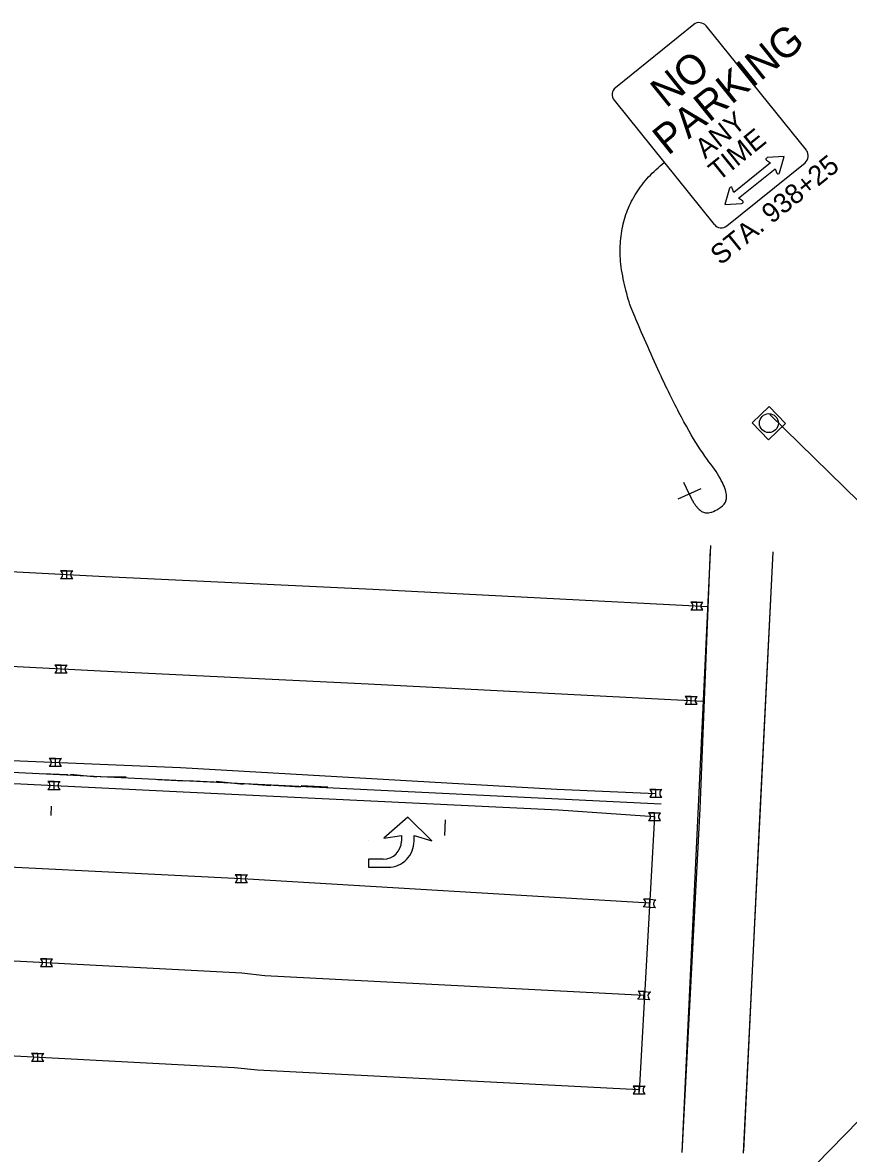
# Model space of a CAD drawing. Extents: x 1847379 to 1850904, y 217032 to 220169.
# Drawn here: x 1847885.3 to 1847990, y 218864.8 to 219008.1 of the extents above; entities that cross this region are included whole.
import ezdxf

# ---------------------------------------------------------------- set-up
doc = ezdxf.new("R2010")
doc.units = 0
for name, color, linetype in [('GE_X_Alignment_100_Stations', 7, 'Continuous'), ('PM_P_Cells', 7, 'Continuous'), ('PM_P_Channelizing_Line', 7, 'Continuous'), ('PM_P_CL_Double_Solid', 7, 'Continuous'), ('PM_P_Crosswalk', 7, 'Continuous'), ('PM_P_Edge_Line', 7, 'Continuous'), ('PM_P_Lane_Line', 7, 'Continuous'), ('PM_P_Stop_Line', 7, 'Continuous'), ('PM_X_Cells', 7, 'Continuous'), ('PM_X_Crosswalk', 7, 'Continuous'), ('RD_X_Bumper_Block', 7, 'Continuous'), ('SG_X_Wiring', 7, 'Continuous'), ('SN_X_Foundation', 7, 'Continuous'), ('SN_X_Public', 7, 'Continuous')]:
    doc.layers.add(name, color=color, linetype=linetype)

msp = doc.modelspace()

# ---------------------------------------------------------------- linework, layer by layer
at = {"layer": 'GE_X_Alignment_100_Stations'}
for p, q in [((1847888.88, 218907.64), (1847888.95, 218908.84)), ((1847938.82, 218905.09), (1847938.92, 218907.09))]:
    msp.add_line(p, q, dxfattribs=at)
at = {"layer": 'PM_P_Cells'}
for p, q in [((1847890.87, 218938.66), (1847890.1, 218938.66)), ((1847890.1, 218938.66), (1847890.87, 218938.66)), ((1847890.87, 218938.66), (1847891.64, 218938.66)), ((1847890.87, 218937.68), (1847890.87, 218938.66)), ((1847890.1, 218937.68), (1847890.87, 218937.68)), ((1847890.1, 218937.68), (1847890.87, 218937.68)), ((1847890.87, 218937.68), (1847891.64, 218937.68)), ((1847970.77, 218934.69), (1847970, 218934.69)), ((1847970, 218934.69), (1847970.77, 218934.69)), ((1847970, 218933.71), (1847970.77, 218933.71)), ((1847970, 218933.71), (1847970.77, 218933.71)), ((1847970.77, 218934.69), (1847971.54, 218934.69)), ((1847970.77, 218933.71), (1847970.77, 218934.69)), ((1847970.77, 218933.71), (1847971.54, 218933.71)), ((1847890.15, 218926.71), (1847889.38, 218926.71)), ((1847889.38, 218926.71), (1847890.15, 218926.71)), ((1847890.15, 218926.71), (1847890.92, 218926.71)), ((1847890.15, 218925.73), (1847890.15, 218926.71)), ((1847889.38, 218925.73), (1847890.15, 218925.73)), ((1847889.38, 218925.73), (1847890.15, 218925.73)), ((1847890.15, 218925.73), (1847890.92, 218925.73)), ((1847970.05, 218922.73), (1847969.28, 218922.73)), ((1847969.28, 218922.73), (1847970.05, 218922.73)), ((1847970.05, 218922.73), (1847970.83, 218922.73)), ((1847970.05, 218921.76), (1847970.05, 218922.73)), ((1847969.28, 218921.76), (1847970.05, 218921.76)), ((1847969.28, 218921.76), (1847970.05, 218921.76)), ((1847970.05, 218921.76), (1847970.83, 218921.76)), ((1847889.44, 218914.87), (1847888.67, 218914.87)), ((1847888.67, 218914.87), (1847889.44, 218914.87)), ((1847888.67, 218913.89), (1847889.44, 218913.89)), ((1847888.67, 218913.89), (1847889.44, 218913.89)), ((1847889.44, 218914.87), (1847890.21, 218914.87)), ((1847889.44, 218913.89), (1847889.44, 218914.87)), ((1847889.44, 218913.89), (1847890.21, 218913.89)), ((1847889.26, 218911.93), (1847888.49, 218911.93)), ((1847888.49, 218911.93), (1847889.26, 218911.93)), ((1847888.49, 218910.95), (1847889.26, 218910.95)), ((1847888.49, 218910.95), (1847889.26, 218910.95)), ((1847889.26, 218911.93), (1847890.03, 218911.93)), ((1847889.26, 218910.95), (1847889.26, 218911.93)), ((1847889.26, 218910.95), (1847890.03, 218910.95)), ((1847965.57, 218910.94), (1847964.8, 218910.94)), ((1847964.8, 218910.94), (1847965.57, 218910.94)), ((1847965.57, 218910.94), (1847966.34, 218910.94)), ((1847965.57, 218909.96), (1847965.57, 218910.94)), ((1847964.8, 218909.96), (1847965.57, 218909.96)), ((1847964.8, 218909.96), (1847965.57, 218909.96)), ((1847965.57, 218909.96), (1847966.34, 218909.96)), ((1847965.4, 218907.99), (1847964.63, 218907.99)), ((1847964.63, 218907.99), (1847965.4, 218907.99)), ((1847965.4, 218907.99), (1847966.17, 218907.99)), ((1847965.4, 218907.02), (1847965.4, 218907.99)), ((1847934.11, 218907.43), (1847931.07, 218904.76)), ((1847937.15, 218904.43), (1847934.11, 218907.43)), ((1847964.63, 218907.02), (1847965.4, 218907.02)), ((1847964.63, 218907.02), (1847965.4, 218907.02)), ((1847965.4, 218907.02), (1847966.17, 218907.02)), ((1847931.07, 218904.76), (1847933.31, 218905.09)), ((1847933.31, 218905.09), (1847933.31, 218904.39)), ((1847934.91, 218904.43), (1847934.91, 218905.09)), ((1847934.91, 218905.09), (1847937.15, 218904.43)), ((1847929.15, 218904.43), (1847929.15, 218904.43)), ((1847937.15, 218904.43), (1847937.15, 218904.43)), ((1847931.01, 218902.09), (1847929.15, 218902.09)), ((1847929.15, 218902.09), (1847929.15, 218901.09)), ((1847929.15, 218901.09), (1847931.63, 218901.09)), ((1847913, 218900.11), (1847912.23, 218900.11)), ((1847912.23, 218900.11), (1847913, 218900.11)), ((1847913, 218900.11), (1847913.77, 218900.11)), ((1847913, 218899.13), (1847913, 218900.11)), ((1847912.23, 218899.13), (1847913, 218899.13)), ((1847912.23, 218899.13), (1847913, 218899.13)), ((1847913, 218899.13), (1847913.77, 218899.13)), ((1847964.82, 218897.02), (1847964.05, 218897.07)), ((1847964.05, 218897.07), (1847964.82, 218897.02)), ((1847964.75, 218896.04), (1847964.82, 218897.02)), ((1847964.82, 218897.02), (1847965.59, 218896.96)), ((1847963.98, 218896.09), (1847964.75, 218896.04)), ((1847963.98, 218896.09), (1847964.75, 218896.04)), ((1847964.75, 218896.04), (1847965.52, 218895.99)), ((1847888.31, 218889.47), (1847887.54, 218889.47)), ((1847887.54, 218889.47), (1847888.31, 218889.47)), ((1847888.31, 218889.47), (1847889.08, 218889.47)), ((1847888.31, 218888.49), (1847888.31, 218889.47)), ((1847887.54, 218888.49), (1847888.31, 218888.49)), ((1847887.54, 218888.49), (1847888.31, 218888.49)), ((1847888.31, 218888.49), (1847889.08, 218888.49)), ((1847964.11, 218885.33), (1847963.34, 218885.39)), ((1847963.34, 218885.39), (1847964.11, 218885.33)), ((1847964.04, 218884.36), (1847964.11, 218885.33)), ((1847964.11, 218885.33), (1847964.88, 218885.27)), ((1847963.27, 218884.41), (1847964.04, 218884.36)), ((1847963.27, 218884.41), (1847964.04, 218884.36)), ((1847964.04, 218884.36), (1847964.81, 218884.3)), ((1847887.19, 218877.48), (1847886.42, 218877.48)), ((1847886.42, 218877.48), (1847887.19, 218877.48)), ((1847886.42, 218876.51), (1847887.19, 218876.51)), ((1847886.42, 218876.51), (1847887.19, 218876.51)), ((1847887.19, 218877.48), (1847887.96, 218877.48)), ((1847887.19, 218876.51), (1847887.19, 218877.48)), ((1847887.19, 218876.51), (1847887.96, 218876.51)), ((1847963.46, 218873.35), (1847962.69, 218873.35)), ((1847962.69, 218873.35), (1847963.46, 218873.35)), ((1847962.69, 218872.37), (1847963.46, 218872.37)), ((1847962.69, 218872.37), (1847963.46, 218872.37)), ((1847963.46, 218873.35), (1847964.23, 218873.35)), ((1847963.46, 218872.37), (1847963.46, 218873.35)), ((1847963.46, 218872.37), (1847964.23, 218872.37))]:
    msp.add_line(p, q, dxfattribs=at)
msp.add_lwpolyline([(1847966.24, 218909.06), (1847864.82, 218914.02), (1847726.41, 218921.61), (1847615.2, 218928.22)], dxfattribs=at)
for centre, radius, start, end in [((1847889.79, 218938.17), 0.576, 301.9738, 58.0262), ((1847889.79, 218938.17), 0.576, 301.9738, 58.0262), ((1847891.94, 218938.17), 0.576, 121.9738, 238.0262), ((1847969.7, 218934.2), 0.576, 301.9738, 58.0262), ((1847969.7, 218934.2), 0.576, 301.9738, 58.0262), ((1847971.85, 218934.2), 0.576, 121.9738, 238.0262), ((1847889.07, 218926.22), 0.576, 301.9738, 58.0262), ((1847889.07, 218926.22), 0.576, 301.9738, 58.0262), ((1847891.22, 218926.22), 0.576, 121.9738, 238.0262), ((1847968.98, 218922.25), 0.576, 301.9738, 58.0262), ((1847968.98, 218922.25), 0.576, 301.9738, 58.0262), ((1847971.13, 218922.25), 0.576, 121.9738, 238.0262), ((1847888.36, 218914.38), 0.576, 301.9738, 58.0262), ((1847888.36, 218914.38), 0.576, 301.9738, 58.0262), ((1847890.51, 218914.38), 0.576, 121.9738, 238.0262), ((1847888.19, 218911.44), 0.576, 301.9738, 58.0262), ((1847888.19, 218911.44), 0.576, 301.9738, 58.0262), ((1847890.34, 218911.44), 0.576, 121.9738, 238.0262), ((1847964.49, 218910.45), 0.576, 301.9738, 58.0262), ((1847964.49, 218910.45), 0.576, 301.9738, 58.0262), ((1847966.64, 218910.45), 0.576, 121.9738, 238.0262), ((1847964.33, 218907.5), 0.576, 301.9738, 58.0262), ((1847964.33, 218907.5), 0.576, 301.9738, 58.0262), ((1847966.48, 218907.5), 0.576, 121.9738, 238.0262), ((1847931.01, 218904.39), 2.3, 270, 360), ((1847931.63, 218904.37), 3.28, 270, 0.9085), ((1847911.93, 218899.62), 0.576, 301.9738, 58.0262), ((1847911.93, 218899.62), 0.576, 301.9738, 58.0262), ((1847914.08, 218899.62), 0.576, 121.9738, 238.0262), ((1847963.71, 218896.6), 0.576, 297.9977, 54.05), ((1847963.71, 218896.6), 0.576, 297.9977, 54.05), ((1847965.86, 218896.45), 0.576, 117.9977, 234.05), ((1847887.23, 218888.98), 0.576, 301.9738, 58.0262), ((1847887.23, 218888.98), 0.576, 301.9738, 58.0262), ((1847889.39, 218888.98), 0.576, 121.9738, 238.0262), ((1847963, 218884.92), 0.576, 297.8201, 53.8724), ((1847963, 218884.92), 0.576, 297.8201, 53.8724), ((1847965.15, 218884.77), 0.576, 117.8201, 233.8724), ((1847886.12, 218876.99), 0.576, 301.9738, 58.0262), ((1847886.12, 218876.99), 0.576, 301.9738, 58.0262), ((1847888.27, 218876.99), 0.576, 121.9738, 238.0262), ((1847962.38, 218872.86), 0.576, 301.9738, 58.0262), ((1847962.38, 218872.86), 0.576, 301.9738, 58.0262), ((1847964.53, 218872.86), 0.576, 121.9738, 238.0262)]:
    msp.add_arc(centre, radius, start, end, dxfattribs=at)
at = {"layer": 'PM_P_Channelizing_Line'}
msp.add_lwpolyline([(1847964.79, 218896.53), (1847913.83, 218899.57), (1847868.37, 218901.85), (1847801.67, 218905.51), (1847760.88, 218907.57), (1847747.13, 218908.37), (1847700.27, 218911.19), (1847652.77, 218914.09), (1847633.42, 218915.04)], dxfattribs=at)
at = {"layer": 'PM_P_CL_Double_Solid'}
for points in [[(1847490, 218937.41), (1847521.99, 218935.72), (1847549.87, 218933.62), (1847611.92, 218929.38), (1847659.1, 218926.63), (1847712.21, 218923.52), (1847759.64, 218920.72), (1847810.63, 218918.2), (1847858.38, 218915.68), (1847905.32, 218913.72), (1847953.04, 218910.96), (1847965.57, 218910.45)], [(1847489.25, 218926.47), (1847521.5, 218924.19), (1847547.23, 218922.25), (1847572.89, 218923.43), (1847613.93, 218927.4), (1847658.9, 218924.58), (1847711.95, 218921.4), (1847759.89, 218918.36), (1847810.62, 218915.58), (1847858.37, 218912.98), (1847905.65, 218910.62), (1847953.25, 218908.34), (1847965.4, 218907.5)]]:
    msp.add_lwpolyline(points, dxfattribs=at)
at = {"layer": 'PM_P_Crosswalk'}
for p, q in [((1847972.51, 218941.88), (1847968.88, 218864.98)), ((1847980.4, 218941.05), (1847976.66, 218864.85))]:
    msp.add_line(p, q, dxfattribs=at)
at = {"layer": 'PM_P_Edge_Line'}
for points in [[(1847552.47, 218957.76), (1847602.87, 218954.43), (1847648.99, 218950.94), (1847698.22, 218948.16), (1847749.1, 218945.08), (1847799.04, 218942.57), (1847847.68, 218940.46), (1847895.74, 218937.94), (1847929.69, 218936.33), (1847972.19, 218934.13)], [(1847963.46, 218872.86), (1847915.07, 218875.36), (1847912.14, 218875.67), (1847866.67, 218878.08), (1847793.75, 218882.07), (1847746.55, 218884.86), (1847706.33, 218887.44), (1847651.18, 218890.91), (1847631.45, 218892.5), (1847577.19, 218896.26), (1847520.38, 218900.5), (1847487.61, 218902.76)]]:
    msp.add_lwpolyline(points, dxfattribs=at)
at = {"layer": 'PM_P_Lane_Line'}
for points in [[(1847490.83, 218949.44), (1847551.31, 218945.81), (1847602.03, 218942.46), (1847648.2, 218938.97), (1847697.52, 218936.18), (1847748.44, 218933.1), (1847798.48, 218930.58), (1847847.11, 218928.48), (1847895.15, 218925.96), (1847929.1, 218924.34), (1847971.57, 218922.14)], [(1847964.08, 218884.84), (1847916.01, 218887.33), (1847913.09, 218887.64), (1847867.32, 218890.07), (1847794.43, 218894.05), (1847747.29, 218896.84), (1847707.09, 218899.42), (1847652.04, 218902.88), (1847632.34, 218904.47), (1847578.05, 218908.23), (1847521.24, 218912.47), (1847488.44, 218914.73)]]:
    msp.add_lwpolyline(points, dxfattribs=at)
at = {"layer": 'PM_P_Stop_Line'}
msp.add_line((1847965.4, 218907.5), (1847963.45, 218872.64), dxfattribs=at)
at = {"layer": 'PM_X_Cells'}
for p, q in [((1847934.11, 218907.43), (1847931.07, 218904.76)), ((1847937.15, 218904.43), (1847934.11, 218907.43)), ((1847931.07, 218904.76), (1847933.31, 218905.09)), ((1847933.31, 218905.09), (1847933.31, 218904.39)), ((1847934.91, 218904.43), (1847934.91, 218905.09)), ((1847934.91, 218905.09), (1847937.15, 218904.43)), ((1847929.15, 218904.43), (1847929.15, 218904.43)), ((1847937.15, 218904.43), (1847937.15, 218904.43)), ((1847931.01, 218902.09), (1847929.15, 218902.09)), ((1847929.15, 218902.09), (1847929.15, 218901.09)), ((1847929.15, 218901.09), (1847931.63, 218901.09))]:
    msp.add_line(p, q, dxfattribs=at)
for centre, radius, end in [((1847931.01, 218904.39), 2.3, 0), ((1847931.63, 218904.37), 3.28, 0.9085)]:
    msp.add_arc(centre, radius, 270, end, dxfattribs=at)
at = {"layer": 'PM_X_Crosswalk'}
for points in [[(1847972.48, 218941.4), (1847971.17, 218908.5), (1847968.87, 218864.92)], [(1847980.4, 218941.07), (1847978.75, 218908.12), (1847976.67, 218865.14)]]:
    msp.add_lwpolyline(points, dxfattribs=at)
at = {"layer": 'RD_X_Bumper_Block'}
for points in [[(1847891.03, 218912.78), (1847887.74, 218912.91)], [(1847894.71, 218912.51), (1847891.34, 218912.83)], [(1847898.41, 218912.51), (1847895.1, 218912.54)], [(1847902.12, 218912.2), (1847898.65, 218912.36)], [(1847905.78, 218912.01), (1847902.44, 218912.18)], [(1847909.56, 218911.86), (1847906.07, 218912.04)], [(1847913.29, 218911.57), (1847909.83, 218911.96)], [(1847916.74, 218911.38), (1847913.4, 218911.66)], [(1847920.52, 218911.23), (1847917.11, 218911.43)], [(1847923.98, 218911.22), (1847920.6, 218911.38)]]:
    msp.add_lwpolyline(points, dxfattribs=at)
at = {"layer": 'SG_X_Wiring'}
for p, q in [((1847999.88, 218939.03), (1847980.01, 218958.48)), ((1847991.33, 218868.98), (1847969.6, 218846.82))]:
    msp.add_line(p, q, dxfattribs=at)
at = {"layer": 'SN_X_Foundation'}
msp.add_lwpolyline([(1847979.87, 218955.25), (1847982.03, 218957.33), (1847979.94, 218959.49), (1847977.78, 218957.41)], close=True, dxfattribs=at)
msp.add_circle((1847979.91, 218957.37), 1.2, dxfattribs=at)
at = {"layer": 'SN_X_Public'}
for p, q in [((1847981.86, 218991.16), (1847979.7, 218991.02)), ((1847981.26, 218989.08), (1847981.86, 218991.16)), ((1847980.1, 218990.35), (1847975.47, 218986.62)), ((1847979.61, 218990.68), (1847980.11, 218990.35)), ((1847980.11, 218990.35), (1847980.1, 218990.35)), ((1847980.7, 218989.62), (1847980.91, 218989.06)), ((1847974.91, 218987.16), (1847974.31, 218985.08)), ((1847975.47, 218986.62), (1847975.26, 218987.17)), ((1847978.08, 218988.12), (1847978.08, 218988.12)), ((1847975.47, 218986.62), (1847975.48, 218986.62)), ((1847976.56, 218985.56), (1847976.06, 218985.89)), ((1847974.31, 218985.08), (1847976.47, 218985.22)), ((1847969.8, 218948.39), (1847969.13, 218949.84)), ((1847971.26, 218949.06), (1847968.35, 218947.72))]:
    msp.add_line(p, q, dxfattribs=at)
for points in [[(1847970.38, 219007.88), (1847960.45, 218999.88)], [(1847984.67, 218991.95), (1847971.96, 219007.71)], [(1847960.28, 218998.3), (1847972.99, 218982.53)], [(1847974.57, 218982.36), (1847984.5, 218990.36)], [(1847976.06, 218985.89), (1847980.69, 218989.62)]]:
    msp.add_lwpolyline(points, dxfattribs=at)
for centre, radius, start, end in [((1847971.09, 219007.01), 1.12, 38.8676, 128.8676), ((1847961.16, 218999.01), 1.12, 128.8676, 218.8676), ((1847983.79, 218991.24), 1.12, 308.8676, 38.8676), ((1847979.71, 218990.83), 0.182, 93.7884, 236.5054), ((1847981.08, 218989.13), 0.182, 201.2298, 343.9469), ((1847975.09, 218987.11), 0.182, 21.2298, 163.9469), ((1847976.46, 218985.4), 0.182, 273.7884, 56.5054), ((1847973.87, 218983.24), 1.12, 218.8676, 308.8676)]:
    msp.add_arc(centre, radius, start, end, dxfattribs=at)
msp.add_open_spline([(1847969.8, 218948.39), (1847970.52, 218946.74), (1847972.31, 218945.6), (1847975.68, 218948.08), (1847968.74, 218957.18), (1847957.62, 218983.19), (1847966.64, 218990.42)], degree=2, dxfattribs=at)

# ---------------------------------------------------------------- texts
for s, height, rotation, p in [('PARKING', 3.75, 38.8676, (1847967.12, 218991.2)), ('NO', 3.75, 38.8676, (1847966.86, 218997.22)), ('ANY', 2.5, 38.8676, (1847971.83, 218990.79)), ('TIME', 2.5, 38.8676, (1847973.54, 218987.95)), ('STA. 938+25', 2.5, 38.9358, (1847973.77, 218977.3))]:
    msp.add_text(s, height=height, rotation=rotation, dxfattribs=at).set_placement(p)

doc.saveas('drawing.dxf')
